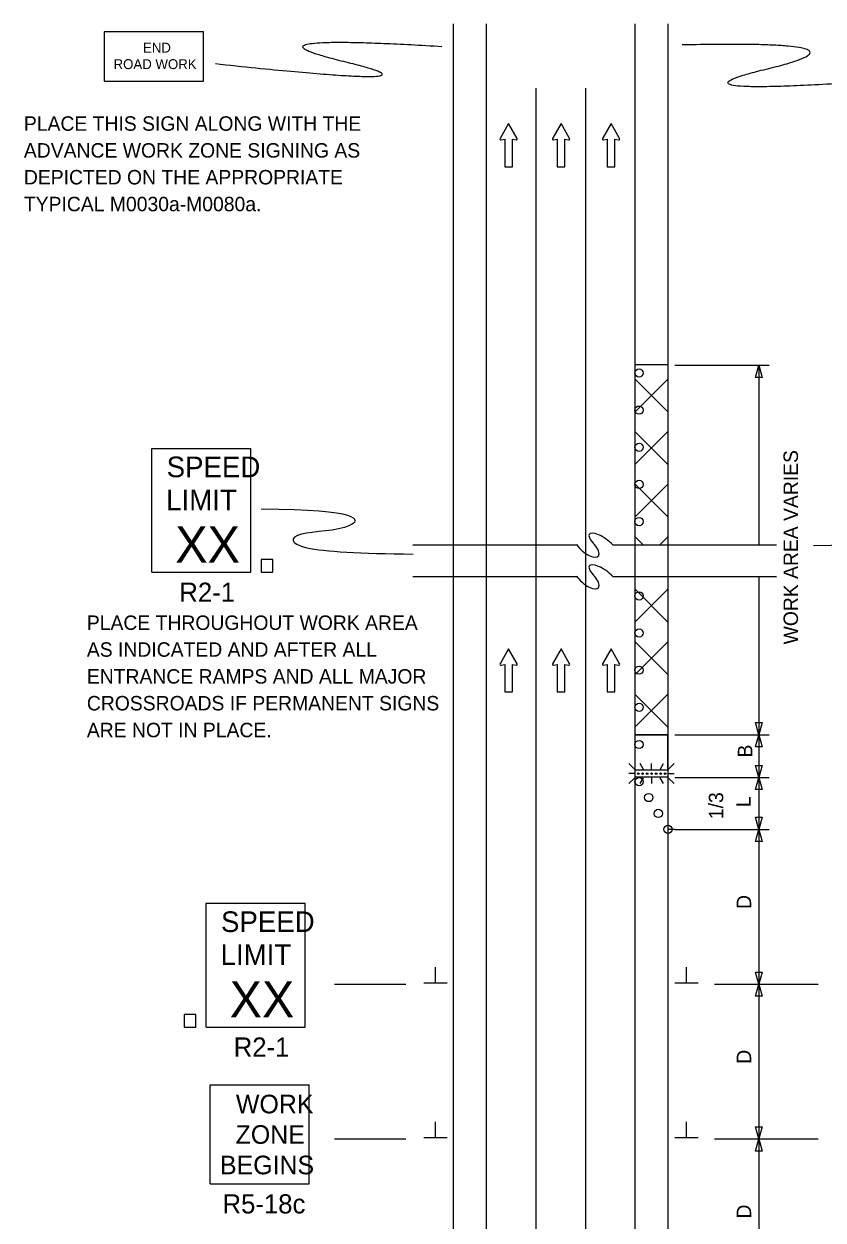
# Model space of a CAD drawing. Extents: x 16738 to 18471, y 7027 to 8193.
# Drawn here: x 16738 to 17125, y 7605 to 8185 of the extents above; entities that cross this region are included whole.
import ezdxf

# ---------------------------------------------------------------- set-up
doc = ezdxf.new("R2010")
doc.units = 0
for name, color, linetype in [('ALI_LEGAL_EX', 7, 'Continuous'), ('MT_SCRATCH_LEVEL_A', 7, 'Continuous'), ('MT_SCRATCH_LEVEL_E', 7, 'Continuous'), ('PAVT_EDGE_EX', 7, 'Continuous'), ('TRAFFIC_SIGNS_PR', 7, 'Continuous'), ('TYPICAL_EX', 7, 'Continuous'), ('TYPICAL_TEXT_DIMEN_PR', 7, 'Continuous')]:
    doc.layers.add(name, color=color, linetype=linetype)

msp = doc.modelspace()

# ---------------------------------------------------------------- linework, layer by layer
at = {"layer": 'ALI_LEGAL_EX'}
for points in [[(16985.65, 8153.48), (16985.65, 8128.48)], [(17009.65, 8153.48), (17009.65, 8128.48)], [(16985.65, 8144.19), (16985.65, 8119.19)], [(16985.65, 8053.48), (16985.65, 8028.48)], [(16985.65, 8053.48), (16985.65, 8028.48)], [(17009.65, 8053.48), (17009.65, 8028.48)], [(16985.65, 7953.48), (16985.65, 7932.2)], [(17009.65, 7953.48), (17009.65, 7928.48)], [(16985.65, 7889.76), (16985.65, 7864.76)], [(16985.65, 7853.48), (16985.65, 7828.48)], [(17009.65, 7853.48), (17009.65, 7828.48)], [(16985.65, 7753.48), (16985.65, 7728.48)], [(17009.65, 7753.48), (17009.65, 7728.48)], [(16985.65, 7653.48), (16985.65, 7628.48)], [(17009.65, 7653.48), (17009.65, 7628.48)]]:
    msp.add_lwpolyline(points, dxfattribs=at)
at = {"layer": 'MT_SCRATCH_LEVEL_A'}
for p, q in [((17049.65, 7996.6), (17033.65, 8012.6)), ((17033.65, 7996.49), (17049.65, 8012.49)), ((17049.65, 7971.15), (17033.65, 7987.15)), ((17033.65, 7971.04), (17049.65, 7987.04)), ((17049.65, 7945.69), (17033.65, 7961.69)), ((17033.65, 7945.58), (17049.65, 7961.58)), ((17037.68, 7932.2), (17033.65, 7936.23)), ((17045.64, 7932.11), (17049.65, 7936.12)), ((17049.65, 7894.78), (17033.65, 7910.78)), ((17033.65, 7894.67), (17049.65, 7910.67)), ((17049.65, 7869.32), (17033.65, 7885.32)), ((17033.65, 7869.21), (17049.65, 7885.21)), ((17049.65, 7843.87), (17033.65, 7859.87)), ((17033.65, 7843.76), (17049.65, 7859.76))]:
    msp.add_line(p, q, dxfattribs=at)
at = {"layer": 'MT_SCRATCH_LEVEL_E'}
for p, q in [((16972.46, 8136.25), (16968.34, 8129.01)), ((16972.46, 8136.25), (16968.34, 8129.01)), ((16976.6, 8129.01), (16972.46, 8136.25)), ((16976.6, 8129.01), (16972.46, 8136.25)), ((16997.88, 8136.25), (16993.77, 8129.01)), ((16997.88, 8136.25), (16993.77, 8129.01)), ((17002.03, 8129.01), (16997.88, 8136.25)), ((17002.03, 8129.01), (16997.88, 8136.25)), ((17022.09, 8136.25), (17017.98, 8129.01)), ((17022.09, 8136.25), (17017.98, 8129.01)), ((17026.24, 8129.01), (17022.09, 8136.25)), ((17026.24, 8129.01), (17022.09, 8136.25)), ((16968.83, 8128.33), (16970.6, 8128.65)), ((16968.83, 8128.33), (16970.6, 8128.65)), ((16970.6, 8128.65), (16970.6, 8115.39)), ((16970.6, 8128.65), (16970.6, 8115.39)), ((16974.35, 8115.39), (16974.35, 8128.65)), ((16974.35, 8128.65), (16976.12, 8128.33)), ((16974.35, 8115.39), (16974.35, 8128.65)), ((16974.35, 8128.65), (16976.12, 8128.33)), ((16994.25, 8128.33), (16996.03, 8128.65)), ((16994.25, 8128.33), (16996.03, 8128.65)), ((16996.03, 8128.65), (16996.03, 8115.39)), ((16996.03, 8128.65), (16996.03, 8115.39)), ((16999.77, 8115.39), (16999.77, 8128.65)), ((16999.77, 8128.65), (17001.55, 8128.33)), ((16999.77, 8115.39), (16999.77, 8128.65)), ((16999.77, 8128.65), (17001.55, 8128.33)), ((17018.47, 8128.33), (17020.24, 8128.65)), ((17018.47, 8128.33), (17020.24, 8128.65)), ((17020.24, 8128.65), (17020.24, 8115.39)), ((17020.24, 8128.65), (17020.24, 8115.39)), ((17023.98, 8115.39), (17023.98, 8128.65)), ((17023.98, 8128.65), (17025.76, 8128.33)), ((17023.98, 8115.39), (17023.98, 8128.65)), ((17023.98, 8128.65), (17025.76, 8128.33)), ((16970.6, 8115.39), (16974.35, 8115.39)), ((16970.6, 8115.39), (16974.35, 8115.39)), ((16996.03, 8115.39), (16999.77, 8115.39)), ((16996.03, 8115.39), (16999.77, 8115.39)), ((17020.24, 8115.39), (17023.98, 8115.39)), ((17020.24, 8115.39), (17023.98, 8115.39)), ((16972.46, 7881.83), (16968.34, 7874.59)), ((16972.46, 7881.83), (16968.34, 7874.59)), ((16976.6, 7874.59), (16972.46, 7881.83)), ((16976.6, 7874.59), (16972.46, 7881.83)), ((16997.88, 7881.83), (16993.77, 7874.59)), ((16997.88, 7881.83), (16993.77, 7874.59)), ((17002.03, 7874.59), (16997.88, 7881.83)), ((17002.03, 7874.59), (16997.88, 7881.83)), ((17022.09, 7881.83), (17017.98, 7874.59)), ((17022.09, 7881.83), (17017.98, 7874.59)), ((17026.24, 7874.59), (17022.09, 7881.83)), ((17026.24, 7874.59), (17022.09, 7881.83)), ((16968.83, 7873.91), (16970.6, 7874.22)), ((16968.83, 7873.91), (16970.6, 7874.22)), ((16970.6, 7874.22), (16970.6, 7860.97)), ((16970.6, 7874.22), (16970.6, 7860.97)), ((16974.35, 7860.97), (16974.35, 7874.22)), ((16974.35, 7874.22), (16976.12, 7873.91)), ((16974.35, 7860.97), (16974.35, 7874.22)), ((16974.35, 7874.22), (16976.12, 7873.91)), ((16994.25, 7873.91), (16996.03, 7874.22)), ((16994.25, 7873.91), (16996.03, 7874.22)), ((16996.03, 7874.22), (16996.03, 7860.97)), ((16996.03, 7874.22), (16996.03, 7860.97)), ((16999.77, 7860.97), (16999.77, 7874.22)), ((16999.77, 7874.22), (17001.55, 7873.91)), ((16999.77, 7860.97), (16999.77, 7874.22)), ((16999.77, 7874.22), (17001.55, 7873.91)), ((17018.47, 7873.91), (17020.24, 7874.22)), ((17018.47, 7873.91), (17020.24, 7874.22)), ((17020.24, 7874.22), (17020.24, 7860.97)), ((17020.24, 7874.22), (17020.24, 7860.97)), ((17023.98, 7860.97), (17023.98, 7874.22)), ((17023.98, 7874.22), (17025.76, 7873.91)), ((17023.98, 7860.97), (17023.98, 7874.22)), ((17023.98, 7874.22), (17025.76, 7873.91)), ((16970.6, 7860.97), (16974.35, 7860.97)), ((16970.6, 7860.97), (16974.35, 7860.97)), ((16996.03, 7860.97), (16999.77, 7860.97)), ((16996.03, 7860.97), (16999.77, 7860.97)), ((17020.24, 7860.97), (17023.98, 7860.97)), ((17020.24, 7860.97), (17023.98, 7860.97))]:
    msp.add_line(p, q, dxfattribs=at)
for centre, start, end in [((16968.75, 8128.79), 150.42484, 279.96381), ((16968.75, 8128.79), 150.42484, 279.96381), ((16976.19, 8128.79), 260.03619, 29.77312), ((16976.19, 8128.79), 260.03619, 29.77312), ((16994.18, 8128.79), 150.42484, 279.96381), ((16994.18, 8128.79), 150.42484, 279.96381), ((17001.62, 8128.79), 260.03619, 29.77312), ((17001.62, 8128.79), 260.03619, 29.77312), ((17018.39, 8128.79), 150.42484, 279.96381), ((17018.39, 8128.79), 150.42484, 279.96381), ((17025.83, 8128.79), 260.03619, 29.77312), ((17025.83, 8128.79), 260.03619, 29.77312), ((16968.75, 7874.37), 150.42484, 279.96381), ((16968.75, 7874.37), 150.42484, 279.96381), ((16976.19, 7874.37), 260.03619, 29.77312), ((16976.19, 7874.37), 260.03619, 29.77312), ((16994.18, 7874.37), 150.42484, 279.96381), ((16994.18, 7874.37), 150.42484, 279.96381), ((17001.62, 7874.37), 260.03619, 29.77312), ((17001.62, 7874.37), 260.03619, 29.77312), ((17018.39, 7874.37), 150.42484, 279.96381), ((17018.39, 7874.37), 150.42484, 279.96381), ((17025.83, 7874.37), 260.03619, 29.77312), ((17025.83, 7874.37), 260.03619, 29.77312)]:
    msp.add_arc(centre, 0.463, start, end, dxfattribs=at)
at = {"layer": 'PAVT_EDGE_EX'}
for p, q in [((16945.65, 8184.57), (16945.65, 7870.68)), ((16961.65, 8184.57), (16961.65, 7870.6)), ((17033.65, 8184.57), (17033.65, 7870.35)), ((17049.65, 8184.57), (17049.65, 7870.6)), ((16985.65, 8140.15), (16985.65, 7272.98)), ((17009.65, 8140.15), (17009.65, 7272.98)), ((16985.65, 8025.46), (16985.65, 7272.98)), ((17009.65, 8025.46), (17009.65, 7272.98)), ((17033.65, 8019.59), (17049.65, 8019.59)), ((17035.65, 7943.44), (17035.65, 7943.44)), ((16945.65, 7870.68), (16945.65, 7350.36)), ((16961.65, 7870.6), (16961.65, 7350.36)), ((17033.65, 7870.35), (17033.65, 7350.36)), ((17049.65, 7870.6), (17049.65, 7350.36)), ((17033.65, 7840.15), (17049.65, 7840.15)), ((17049.65, 7840.15), (17033.65, 7840.15)), ((17033.65, 7840.15), (17033.65, 7823.16)), ((17049.65, 7823.16), (17049.65, 7840.15)), ((17033.65, 7823.16), (17049.65, 7823.16)), ((17033.65, 7823.16), (17049.65, 7823.16)), ((17052.95, 7794.32), (17049.65, 7794.32))]:
    msp.add_line(p, q, dxfattribs=at)
at = {"layer": 'TRAFFIC_SIGNS_PR'}
for p, q in [((16799.74, 7978.86), (16847.74, 7978.86)), ((16799.74, 7918.86), (16799.74, 7978.86)), ((16847.74, 7918.86), (16847.74, 7978.86)), ((16799.74, 7918.86), (16847.74, 7918.86)), ((17030.76, 7826.2), (17033.58, 7823.38)), ((17037.85, 7823.38), (17036.22, 7826.2)), ((17041.67, 7823.38), (17041.67, 7826.2)), ((17045.8, 7823.38), (17047.43, 7826.2)), ((17049.75, 7823.38), (17052.57, 7826.2)), ((17033.58, 7821.35), (17030.76, 7821.35)), ((17030.76, 7816.5), (17033.58, 7819.32)), ((17035.22, 7821.35), (17035.22, 7821.35)), ((17036.2, 7816.5), (17037.83, 7819.32)), ((17037.4, 7821.35), (17037.4, 7821.35)), ((17039.57, 7821.35), (17039.57, 7821.35)), ((17041.67, 7819.32), (17041.67, 7816.5)), ((17041.74, 7821.35), (17041.74, 7821.35)), ((17043.92, 7821.35), (17043.92, 7821.35)), ((17047.46, 7816.5), (17045.83, 7819.32)), ((17046.09, 7821.35), (17046.09, 7821.35)), ((17048.26, 7821.35), (17048.26, 7821.35)), ((17049.75, 7821.35), (17052.57, 7821.35)), ((17049.75, 7819.32), (17052.57, 7816.5)), ((16826.06, 7758.49), (16874.06, 7758.49)), ((16826.06, 7698.49), (16826.06, 7758.49)), ((16874.06, 7698.49), (16874.06, 7758.49)), ((16826.06, 7698.49), (16874.06, 7698.49)), ((16827.98, 7622.5), (16827.98, 7670.5)), ((16827.98, 7670.5), (16875.98, 7670.5)), ((16875.98, 7622.5), (16875.98, 7670.5)), ((16827.98, 7622.5), (16875.98, 7622.5))]:
    msp.add_line(p, q, dxfattribs=at)
for points in [[(16776.73, 8156.76), (16824.73, 8156.76), (16824.73, 8180.76), (16776.73, 8180.76)], [(16852.75, 7918.86), (16858.35, 7918.86), (16858.35, 7925.03), (16852.75, 7925.03)], [(17049.52, 7819.55), (17033.81, 7819.55), (17033.81, 7823.15), (17049.52, 7823.15)], [(16815.45, 7698.49), (16821.05, 7698.49), (16821.05, 7704.66), (16815.45, 7704.66)]]:
    msp.add_lwpolyline(points, close=True, dxfattribs=at)
for centre, radius in [((17035.65, 8015.44), 2), ((17035.65, 7997.44), 2), ((17035.65, 7979.44), 2), ((17035.65, 7961.44), 2), ((17035.65, 7943.44), 2), ((17035.65, 7907.44), 2), ((17035.65, 7889.44), 2), ((17035.65, 7871.44), 2), ((17035.65, 7853.44), 2), ((17035.65, 7835.44), 2), ((17035.65, 7817.44), 2), ((17035.7, 7817.44), 2), ((17035.24, 7821.35), 0.379), ((17037.39, 7821.35), 0.379), ((17039.57, 7821.35), 0.379), ((17041.74, 7821.35), 0.379), ((17043.91, 7821.35), 0.379), ((17046.09, 7821.35), 0.379), ((17048.26, 7821.35), 0.379), ((17040.35, 7809.73), 2), ((17044.99, 7802.03), 2), ((17049.65, 7794.32), 2)]:
    msp.add_circle(centre, radius, dxfattribs=at)
for points in [[(16830.54, 8165.34), (16949.91, 8152.45), (16836, 8180.03), (16940.24, 8173.68)], [(17155.78, 8157.21), (17040.56, 8148.97), (17154.47, 8176.55), (17056.53, 8174.38)]]:
    msp.add_open_spline(points, degree=2, dxfattribs=at)
at = {"layer": 'TYPICAL_EX'}
for p, q in [((16926.17, 7932.2), (17005.48, 7932.2)), ((17022.9, 7932.2), (17102.17, 7932.2)), ((16926.17, 7916.88), (17005.48, 7916.88)), ((17022.9, 7916.88), (17102.17, 7916.88))]:
    msp.add_line(p, q, dxfattribs=at)
for centre, major_axis, ratio, start_param, end_param in [((17018.27, 7932.47), (6.66, -4.85), 0.346236, 1.077134, 4.299707), ((17010.23, 7931.66), (-5.67, 4.94), 0.423114, 0.994299, 4.377734), ((17018.27, 7917.15), (6.66, -4.85), 0.346236, 1.077134, 4.299707), ((17010.23, 7916.34), (-5.67, 4.94), 0.423114, 0.994299, 4.377734)]:
    msp.add_ellipse(centre, major_axis=major_axis, ratio=ratio, start_param=start_param, end_param=end_param, dxfattribs=at)
at = {"layer": 'TYPICAL_TEXT_DIMEN_PR'}
for p, q in [((17052.95, 8019.19), (17098.65, 8019.19)), ((17092.08, 8013.32), (17093.65, 8019.19)), ((17093.65, 8019.19), (17095.22, 8013.32)), ((17093.65, 8019.19), (17093.65, 7932)), ((17093.65, 8013.32), (17092.08, 8013.32)), ((17095.22, 8013.32), (17093.65, 8013.32)), ((17093.65, 7916.84), (17093.65, 7840.15)), ((17093.65, 7840.15), (17092.08, 7846.01)), ((17092.08, 7846.01), (17093.65, 7846.01)), ((17093.65, 7846.01), (17095.22, 7846.01)), ((17095.22, 7846.01), (17093.65, 7840.15)), ((17052.95, 7840.15), (17098.65, 7840.15)), ((17092.08, 7834.28), (17093.65, 7840.15)), ((17093.65, 7840.15), (17093.65, 7819.44)), ((17093.65, 7840.15), (17095.22, 7834.28)), ((17093.65, 7834.28), (17092.08, 7834.28)), ((17095.22, 7834.28), (17093.65, 7834.28)), ((17093.65, 7819.44), (17092.08, 7825.3)), ((17092.08, 7825.3), (17093.65, 7825.3)), ((17093.65, 7825.3), (17095.22, 7825.3)), ((17095.22, 7825.3), (17093.65, 7819.44)), ((17052.95, 7819.44), (17098.65, 7819.44)), ((17092.08, 7813.58), (17093.65, 7819.44)), ((17093.65, 7819.44), (17093.65, 7794.32)), ((17093.65, 7819.44), (17095.22, 7813.58)), ((17093.65, 7813.58), (17092.08, 7813.58)), ((17095.22, 7813.58), (17093.65, 7813.58)), ((17093.65, 7794.32), (17092.08, 7800.18)), ((17092.08, 7800.18), (17093.65, 7800.18)), ((17093.65, 7800.18), (17095.22, 7800.18)), ((17095.22, 7800.18), (17093.65, 7794.32)), ((17052.95, 7794.32), (17098.65, 7794.32)), ((17092.08, 7788.46), (17093.65, 7794.32)), ((17093.65, 7794.32), (17093.65, 7719.32)), ((17093.65, 7794.32), (17095.22, 7788.46)), ((17093.65, 7788.46), (17092.08, 7788.46)), ((17095.22, 7788.46), (17093.65, 7788.46)), ((16937.08, 7719.81), (16937.08, 7727.6)), ((17058.58, 7719.81), (17058.58, 7727.6)), ((17093.65, 7719.32), (17092.08, 7725.18)), ((17092.08, 7725.18), (17093.65, 7725.18)), ((17093.65, 7725.18), (17095.22, 7725.18)), ((17095.22, 7725.18), (17093.65, 7719.32)), ((16888.17, 7719.32), (16922.79, 7719.32)), ((16942.7, 7719.81), (16931.45, 7719.81)), ((17064.21, 7719.81), (17052.96, 7719.81)), ((17072.13, 7719.32), (17122.32, 7719.32)), ((17092.08, 7713.46), (17093.65, 7719.32)), ((17093.65, 7719.32), (17093.65, 7644.32)), ((17093.65, 7719.32), (17095.22, 7713.46)), ((17093.65, 7713.46), (17092.08, 7713.46)), ((17095.22, 7713.46), (17093.65, 7713.46)), ((16937.08, 7644.88), (16937.08, 7652.66)), ((17058.58, 7644.88), (17058.58, 7652.66)), ((16942.7, 7644.88), (16931.45, 7644.88)), ((17064.21, 7644.88), (17052.96, 7644.88)), ((17093.65, 7644.32), (17092.08, 7650.18)), ((17092.08, 7650.18), (17093.65, 7650.18)), ((17093.65, 7650.18), (17095.22, 7650.18)), ((17095.22, 7650.18), (17093.65, 7644.32)), ((16888.17, 7644.32), (16922.79, 7644.32)), ((17072.13, 7644.32), (17122.32, 7644.32)), ((17092.08, 7638.46), (17093.65, 7644.32)), ((17093.65, 7644.32), (17093.65, 7569.32)), ((17093.65, 7644.32), (17095.22, 7638.46)), ((17093.65, 7638.46), (17092.08, 7638.46)), ((17095.22, 7638.46), (17093.65, 7638.46))]:
    msp.add_line(p, q, dxfattribs=at)
for points in [[(17120.14, 7931.87), (17168.61, 7931.87), (17168.61, 7942.62), (17133.69, 7942.62), (17133.69, 7951.67), (17167.9, 7953.43), (17182.62, 7953.72)], [(16852.78, 7949.54), (16901.25, 7949.54), (16901.25, 7938.78), (16866.33, 7938.78), (16866.33, 7929.73), (16900.54, 7927.97), (16926.31, 7927.68)]]:
    msp.add_open_spline(points, degree=3, dxfattribs=at)

# ---------------------------------------------------------------- texts
at = {"layer": 'TRAFFIC_SIGNS_PR'}
for s, height, p in [('END', 4.789, (16795.49, 8170.67)), ('ROAD WORK', 4.789, (16781.25, 8162.69)), ('PLACE THIS SIGN ALONG WITH THE', 7, (16737.84, 8132.8)), ('ADVANCE WORK ZONE SIGNING AS', 7, (16737.84, 8119.8)), ('DEPICTED ON THE APPROPRIATE', 7, (16737.84, 8106.8)), ('TYPICAL M0030a-M0080a.', 7, (16737.84, 8093.8)), ('SPEED', 10, (16806.95, 7964.93)), ('LIMIT', 10, (16806.74, 7948.93)), ('XX', 17.538, (16811.13, 7923.55)), ('R2-1', 9.3, (16813.08, 7904.56)), ('PLACE THROUGHOUT WORK AREA', 7, (16768.32, 7890.94)), ('AS INDICATED AND AFTER ALL', 7, (16768.32, 7877.94)), ('ENTRANCE RAMPS AND ALL MAJOR', 7, (16768.32, 7864.94)), ('CROSSROADS IF PERMANENT SIGNS', 7, (16768.32, 7851.94)), ('ARE NOT IN PLACE.', 7, (16768.32, 7838.94)), ('SPEED', 10, (16833.27, 7744.57)), ('LIMIT', 10, (16833.07, 7728.57)), ('XX', 17.538, (16837.45, 7703.19)), ('R2-1', 9.3, (16839.41, 7684.19)), ('WORK', 9.021, (16840.49, 7656.71)), ('ZONE', 9.021, (16840.34, 7641.95)), ('BEGINS', 9.021, (16832.75, 7627.18)), ('R5-18c', 9.3, (16834, 7608.2))]:
    msp.add_text(s, height=height, dxfattribs=at).set_placement(p)
at = {"layer": 'TYPICAL_TEXT_DIMEN_PR'}
for s, p in [('WORK AREA VARIES', (17112.58, 7883.93)), ('B', (17090.46, 7829.14)), ('1/3', (17076.41, 7799.27)), ('L', (17089.71, 7805.06)), ('D', (17089.92, 7755.74)), ('D', (17089.92, 7680.74)), ('D', (17089.92, 7605.74))]:
    msp.add_text(s, height=7, rotation=90, dxfattribs=at).set_placement(p)

doc.saveas('drawing.dxf')
